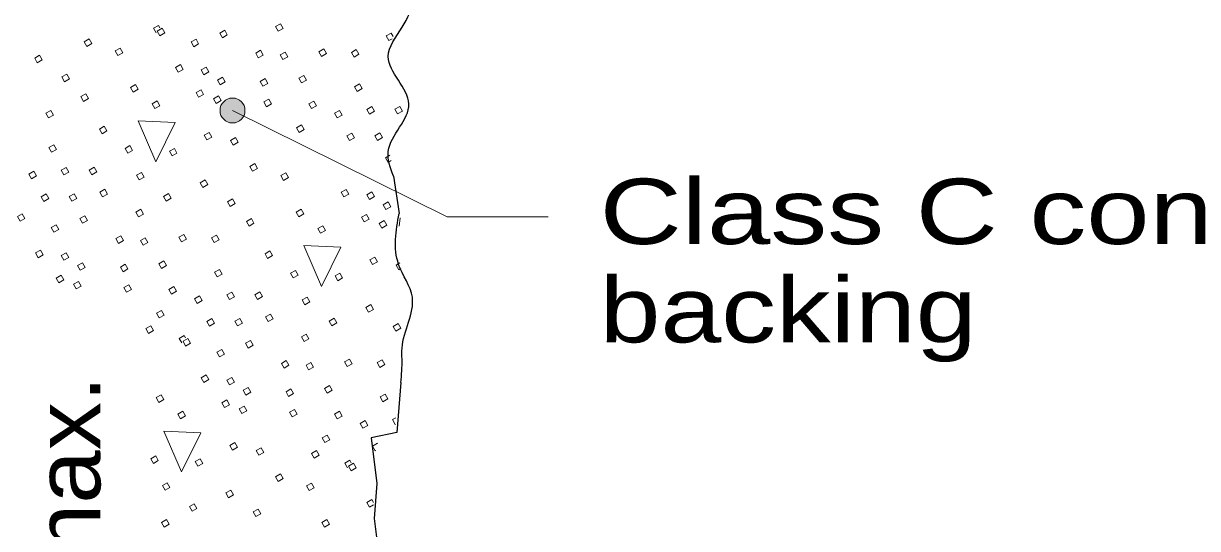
# Model space of a CAD drawing. Extents: x 1170.6 to 1204.6, y 975 to 1019.
# Drawn here: x 1195.183 to 1197.982, y 1000.634 to 1001.839 of the extents above; entities that cross this region are included whole.
import ezdxf
from ezdxf.enums import TextEntityAlignment as Align

# ---------------------------------------------------------------- set-up
doc = ezdxf.new("R2010")
doc.units = 0
doc.header["$LTSCALE"] = 0.062
doc.linetypes.add('LONG_DASHED', pattern=[7.5, 6, -1.5])
doc.layers.add('1', color=7, linetype='Continuous', lineweight=13)

msp = doc.modelspace()

# ---------------------------------------------------------------- hatches: boundary and pattern name
at = {"layer": '1'}
msp.add_hatch(color=256, dxfattribs=at).paths.add_polyline_path([(1195.71138, 1001.6317, 1), (1195.65182, 1001.6317, 1)])

# ---------------------------------------------------------------- linework, layer by layer
for p, q in [((1195.49925, 1001.81725), (1195.49317, 1001.82808)), ((1196.046, 1001.51883), (1196.05642, 1001.52475)), ((1196.07917, 1001.35608), (1196.08125, 1001.37567)), ((1196.0715, 1001.26292), (1196.0805, 1001.268)), ((1195.56058, 1001.077), (1195.5545, 1001.08783)), ((1196.06317, 1000.89408), (1196.07133, 1000.89875)), ((1195.9555, 1000.77942), (1195.94933, 1000.79025))]:
    msp.add_line(p, q, dxfattribs=at)
at = {"layer": '1', "lineweight": 25}
msp.add_line((1196.06508, 1001.47525), (1196.07867, 1001.38617), dxfattribs=at)
at = {"layer": '1'}
for points in [[(1195.49317, 1001.82808), (1195.505, 1001.83483), (1195.50825, 1001.82917)], [(1196.04825, 1001.80983), (1196.06017, 1001.81658), (1196.06475, 1001.80842)], [(1196.06242, 1001.80308), (1196.05467, 1001.79867), (1196.04825, 1001.80983)], [(1195.68158, 1001.63167), (1196.1935, 1001.37825), (1196.43392, 1001.37825)], [(1196.06008, 1001.512), (1196.05233, 1001.50758), (1196.046, 1001.51883)], [(1196.08258, 1001.25433), (1196.07783, 1001.25167), (1196.0715, 1001.26292)], [(1195.5545, 1001.08783), (1195.56633, 1001.09458), (1195.5695, 1001.08892)], [(1196.07008, 1000.88317), (1196.0695, 1000.88283), (1196.06317, 1000.89408)], [(1196.0155, 1000.83083), (1196.02733, 1000.83758), (1196.02742, 1000.83742)], [(1196.023, 1000.82025), (1196.02183, 1000.81958), (1196.0155, 1000.83083)], [(1195.94933, 1000.79025), (1195.96117, 1000.797), (1195.96442, 1000.79133)], [(1196.002, 1000.69658), (1196.01383, 1000.70325), (1196.01767, 1000.69642)], [(1196.01742, 1000.6905), (1196.00833, 1000.68533), (1196.002, 1000.69658)]]:
    msp.add_lwpolyline(points, dxfattribs=at)
for points in [[(1195.7845, 1001.83192), (1195.79633, 1001.83858), (1195.80267, 1001.82733), (1195.79083, 1001.82067)], [(1195.50225, 1001.82125), (1195.51408, 1001.828), (1195.5205, 1001.81675), (1195.50858, 1001.81)], [(1195.65108, 1001.81642), (1195.66292, 1001.82317), (1195.66925, 1001.81192), (1195.65742, 1001.80517)], [(1195.32783, 1001.79575), (1195.33967, 1001.8025), (1195.346, 1001.79125), (1195.33417, 1001.7845)], [(1195.40167, 1001.77375), (1195.4135, 1001.7805), (1195.41983, 1001.76925), (1195.408, 1001.76258)], [(1195.58275, 1001.79525), (1195.59458, 1001.80192), (1195.60092, 1001.79067), (1195.58908, 1001.784)], [(1195.88742, 1001.772), (1195.89925, 1001.77875), (1195.90558, 1001.7675), (1195.89375, 1001.76075)], [(1195.965, 1001.77033), (1195.97683, 1001.77708), (1195.98317, 1001.76583), (1195.97133, 1001.75908)], [(1195.20992, 1001.75692), (1195.22175, 1001.76367), (1195.22808, 1001.75242), (1195.21625, 1001.74567)], [(1195.73683, 1001.76867), (1195.74867, 1001.77533), (1195.755, 1001.76408), (1195.74317, 1001.75742)], [(1195.7955, 1001.76425), (1195.80733, 1001.77092), (1195.81367, 1001.75967), (1195.80183, 1001.753)], [(1195.54583, 1001.73442), (1195.55767, 1001.74117), (1195.564, 1001.72992), (1195.55217, 1001.72317)], [(1195.60683, 1001.72833), (1195.61867, 1001.735), (1195.625, 1001.72375), (1195.61317, 1001.71708)], [(1195.27483, 1001.71167), (1195.28667, 1001.71833), (1195.293, 1001.70717), (1195.28117, 1001.70042)], [(1195.43825, 1001.68683), (1195.45008, 1001.69358), (1195.45642, 1001.68233), (1195.44458, 1001.67567)], [(1195.64575, 1001.70425), (1195.65758, 1001.711), (1195.66392, 1001.69975), (1195.65208, 1001.693)], [(1195.74783, 1001.701), (1195.75967, 1001.70767), (1195.766, 1001.69642), (1195.75417, 1001.68975)], [(1195.83975, 1001.70875), (1195.85158, 1001.7155), (1195.85792, 1001.70425), (1195.84608, 1001.6975)], [(1195.97242, 1001.6885), (1195.98433, 1001.69517), (1195.99067, 1001.68392), (1195.97875, 1001.67725)], [(1195.31983, 1001.66475), (1195.33167, 1001.6715), (1195.338, 1001.66025), (1195.32617, 1001.6535)], [(1195.59458, 1001.6745), (1195.6065, 1001.68117), (1195.61283, 1001.67), (1195.60092, 1001.66325)], [(1195.63633, 1001.65992), (1195.64817, 1001.66667), (1195.6545, 1001.65542), (1195.64267, 1001.64867)], [(1195.49025, 1001.64767), (1195.50208, 1001.65442), (1195.50842, 1001.64317), (1195.49658, 1001.63642)], [(1195.75625, 1001.65208), (1195.76808, 1001.65875), (1195.77442, 1001.64758), (1195.76258, 1001.64083)], [(1195.86358, 1001.6475), (1195.87542, 1001.65417), (1195.88175, 1001.64292), (1195.86992, 1001.63625)], [(1196.00183, 1001.63442), (1196.01375, 1001.64108), (1196.02008, 1001.62983), (1196.00825, 1001.62317)], [(1196.06858, 1001.63475), (1196.08042, 1001.64142), (1196.08675, 1001.63017), (1196.07492, 1001.6235)], [(1195.2365, 1001.62517), (1195.24833, 1001.63192), (1195.25467, 1001.62067), (1195.24283, 1001.61392)], [(1195.92475, 1001.62525), (1195.93658, 1001.63192), (1195.943, 1001.62067), (1195.93108, 1001.614)], [(1195.36417, 1001.5875), (1195.376, 1001.59417), (1195.38233, 1001.583), (1195.3705, 1001.57625)], [(1195.4565, 1001.60692), (1195.499, 1001.50942), (1195.54467, 1001.60317)], [(1195.83408, 1001.59067), (1195.84592, 1001.59742), (1195.85233, 1001.58617), (1195.84042, 1001.57942)], [(1195.61408, 1001.57292), (1195.626, 1001.57958), (1195.63233, 1001.56842), (1195.6205, 1001.56167)], [(1195.67658, 1001.5605), (1195.68842, 1001.56717), (1195.69475, 1001.55592), (1195.68292, 1001.54925)], [(1195.95417, 1001.57108), (1195.96608, 1001.57783), (1195.97242, 1001.56658), (1195.9605, 1001.55992)], [(1196.02092, 1001.57142), (1196.03275, 1001.57817), (1196.03908, 1001.56692), (1196.02725, 1001.56025)], [(1195.24392, 1001.54333), (1195.25583, 1001.55008), (1195.26217, 1001.53883), (1195.25025, 1001.53208)], [(1195.42533, 1001.54108), (1195.43717, 1001.54783), (1195.4435, 1001.53658), (1195.43167, 1001.52992)], [(1195.53108, 1001.53442), (1195.54292, 1001.54117), (1195.54925, 1001.52992), (1195.53742, 1001.52317)], [(1195.72267, 1001.49817), (1195.7345, 1001.50492), (1195.74083, 1001.49367), (1195.729, 1001.48692)], [(1195.19625, 1001.48008), (1195.20817, 1001.48683), (1195.2145, 1001.47558), (1195.20258, 1001.46883)], [(1195.27342, 1001.48925), (1195.28525, 1001.496), (1195.29158, 1001.48475), (1195.27975, 1001.478)], [(1195.34008, 1001.48958), (1195.35192, 1001.49633), (1195.35825, 1001.48508), (1195.34642, 1001.47833)], [(1195.453, 1001.47717), (1195.46483, 1001.48392), (1195.47117, 1001.47267), (1195.45933, 1001.46592)], [(1195.79658, 1001.47625), (1195.80842, 1001.48292), (1195.81475, 1001.47167), (1195.80292, 1001.465)], [(1195.36517, 1001.437), (1195.377, 1001.44367), (1195.38333, 1001.43242), (1195.3715, 1001.42575)], [(1195.60483, 1001.45933), (1195.61667, 1001.46608), (1195.623, 1001.45483), (1195.61117, 1001.44808)], [(1195.94075, 1001.43683), (1195.95258, 1001.44358), (1195.95892, 1001.43233), (1195.94708, 1001.42558)], [(1195.22567, 1001.426), (1195.23758, 1001.43275), (1195.24392, 1001.4215), (1195.23208, 1001.41475)], [(1195.29242, 1001.42633), (1195.30425, 1001.43308), (1195.31058, 1001.42183), (1195.29875, 1001.41508)], [(1195.51742, 1001.42683), (1195.52925, 1001.43358), (1195.53558, 1001.42233), (1195.52375, 1001.41558)], [(1195.66975, 1001.41408), (1195.68158, 1001.42083), (1195.68792, 1001.40958), (1195.67608, 1001.40283)], [(1196.00167, 1001.43075), (1196.01358, 1001.43742), (1196.01992, 1001.42617), (1196.008, 1001.4195)], [(1196.04067, 1001.40667), (1196.0525, 1001.41342), (1196.05883, 1001.40217), (1196.047, 1001.39542)], [(1195.16867, 1001.37858), (1195.1805, 1001.38525), (1195.18683, 1001.374), (1195.175, 1001.36733)], [(1195.45083, 1001.38917), (1195.46275, 1001.39592), (1195.46908, 1001.38467), (1195.45717, 1001.37792)], [(1195.83317, 1001.38933), (1195.845, 1001.396), (1195.85133, 1001.38475), (1195.8395, 1001.37808)], [(1195.24917, 1001.3525), (1195.261, 1001.35925), (1195.26733, 1001.348), (1195.2555, 1001.34125)], [(1195.3175, 1001.37375), (1195.32933, 1001.38042), (1195.33567, 1001.36917), (1195.32383, 1001.3625)], [(1195.71467, 1001.36717), (1195.7265, 1001.37392), (1195.73283, 1001.36267), (1195.721, 1001.35592)], [(1195.9895, 1001.37692), (1196.00133, 1001.38358), (1196.00767, 1001.37242), (1195.99583, 1001.36567)], [(1196.03125, 1001.36233), (1196.04308, 1001.36908), (1196.04942, 1001.35783), (1196.03758, 1001.35117)], [(1195.40317, 1001.32592), (1195.415, 1001.33267), (1195.42142, 1001.32142), (1195.4095, 1001.31467)], [(1195.55383, 1001.32933), (1195.56567, 1001.33608), (1195.572, 1001.32483), (1195.56017, 1001.31808)], [(1195.63142, 1001.32758), (1195.64325, 1001.33433), (1195.64958, 1001.32308), (1195.63775, 1001.31642)], [(1195.88517, 1001.35008), (1195.897, 1001.35683), (1195.90333, 1001.34558), (1195.8915, 1001.33883)], [(1195.46192, 1001.3215), (1195.47375, 1001.32825), (1195.48008, 1001.317), (1195.46825, 1001.31025)], [(1195.85142, 1001.30933), (1195.89392, 1001.21183), (1195.9395, 1001.30558)], [(1195.21225, 1001.29175), (1195.22408, 1001.29842), (1195.23042, 1001.28717), (1195.21858, 1001.2805)], [(1195.27317, 1001.28558), (1195.28508, 1001.29233), (1195.29142, 1001.28108), (1195.27958, 1001.27433)], [(1195.75908, 1001.28992), (1195.77092, 1001.29667), (1195.77725, 1001.28542), (1195.76542, 1001.27867)], [(1196.009, 1001.27533), (1196.02083, 1001.28208), (1196.02717, 1001.27083), (1196.01533, 1001.26408)], [(1195.31217, 1001.26158), (1195.324, 1001.26825), (1195.33033, 1001.25708), (1195.3185, 1001.25033)], [(1195.41425, 1001.25825), (1195.42608, 1001.265), (1195.43242, 1001.25375), (1195.42058, 1001.247)], [(1195.50617, 1001.26608), (1195.518, 1001.27275), (1195.52433, 1001.26158), (1195.5125, 1001.25483)], [(1195.63883, 1001.24575), (1195.65067, 1001.2525), (1195.657, 1001.24125), (1195.64517, 1001.2345)], [(1195.82017, 1001.24358), (1195.832, 1001.25025), (1195.83842, 1001.239), (1195.8265, 1001.23233)], [(1195.261, 1001.23175), (1195.27283, 1001.2385), (1195.27917, 1001.22725), (1195.26733, 1001.2205)], [(1195.30275, 1001.21725), (1195.31458, 1001.224), (1195.32092, 1001.21275), (1195.30908, 1001.206)], [(1195.926, 1001.23683), (1195.93783, 1001.24358), (1195.94417, 1001.23233), (1195.93233, 1001.22558)], [(1195.42267, 1001.20933), (1195.4345, 1001.21608), (1195.44083, 1001.20483), (1195.429, 1001.19817)], [(1195.52992, 1001.20475), (1195.54175, 1001.2115), (1195.54817, 1001.20025), (1195.53625, 1001.1935)], [(1195.59117, 1001.1825), (1195.603, 1001.18925), (1195.60933, 1001.178), (1195.5975, 1001.17125)], [(1195.66825, 1001.19167), (1195.68008, 1001.19842), (1195.68642, 1001.18717), (1195.67458, 1001.18042)], [(1195.73492, 1001.192), (1195.74683, 1001.19875), (1195.75317, 1001.1875), (1195.74133, 1001.18075)], [(1195.84792, 1001.17958), (1195.85975, 1001.18633), (1195.86608, 1001.17508), (1195.85425, 1001.16833)], [(1195.99967, 1001.16175), (1196.0115, 1001.1685), (1196.01783, 1001.15725), (1196.006, 1001.15058)], [(1195.5005, 1001.148), (1195.51233, 1001.15475), (1195.51867, 1001.1435), (1195.50683, 1001.13675)], [(1195.62058, 1001.12842), (1195.63242, 1001.13517), (1195.63875, 1001.12392), (1195.62692, 1001.11717)], [(1195.68725, 1001.12875), (1195.69917, 1001.1355), (1195.7055, 1001.12425), (1195.69358, 1001.1175)], [(1195.76008, 1001.13942), (1195.77192, 1001.14608), (1195.77825, 1001.13492), (1195.76642, 1001.12817)], [(1195.91233, 1001.12925), (1195.92417, 1001.136), (1195.9305, 1001.12475), (1195.91867, 1001.11808)], [(1195.47533, 1001.11117), (1195.48717, 1001.11783), (1195.4935, 1001.10658), (1195.48167, 1001.09992)], [(1196.06467, 1001.1165), (1196.0765, 1001.12325), (1196.08283, 1001.112), (1196.071, 1001.10525)], [(1195.56358, 1001.081), (1195.57542, 1001.08767), (1195.58175, 1001.07642), (1195.56992, 1001.06975)], [(1195.71242, 1001.07617), (1195.72425, 1001.08283), (1195.73058, 1001.07158), (1195.71875, 1001.06492)], [(1195.84575, 1001.09158), (1195.85758, 1001.09833), (1195.86392, 1001.08708), (1195.85208, 1001.08033)], [(1195.64408, 1001.05492), (1195.65592, 1001.06167), (1195.66225, 1001.05042), (1195.65042, 1001.04367)], [(1195.79808, 1001.02833), (1195.80992, 1001.03508), (1195.81625, 1001.02383), (1195.80442, 1001.01708)], [(1195.85683, 1001.02392), (1195.86867, 1001.03067), (1195.875, 1001.01942), (1195.86317, 1001.01267)], [(1195.94875, 1001.03175), (1195.96058, 1001.0385), (1195.96692, 1001.02725), (1195.95508, 1001.0205)], [(1196.02625, 1001.03008), (1196.03817, 1001.03675), (1196.0445, 1001.0255), (1196.03267, 1001.01883)], [(1195.60708, 1000.99417), (1195.61892, 1001.00083), (1195.62533, 1000.98958), (1195.61342, 1000.98292)], [(1195.66808, 1000.988), (1195.67992, 1000.99475), (1195.68625, 1000.9835), (1195.67442, 1000.97675)], [(1195.707, 1000.964), (1195.71892, 1000.97075), (1195.72525, 1000.9595), (1195.71342, 1000.95275)], [(1195.80917, 1000.96067), (1195.821, 1000.96742), (1195.82733, 1000.95617), (1195.8155, 1000.94942)], [(1195.90108, 1000.9685), (1195.91292, 1000.97525), (1195.91925, 1000.964), (1195.90742, 1000.95725)], [(1195.49958, 1000.94658), (1195.51142, 1000.95333), (1195.51775, 1000.94208), (1195.50592, 1000.93533)], [(1195.65592, 1000.93417), (1195.66775, 1000.94092), (1195.67408, 1000.92967), (1195.66225, 1000.923)], [(1196.03375, 1000.94817), (1196.04558, 1000.95492), (1196.05192, 1000.94367), (1196.04008, 1000.93692)], [(1195.55158, 1000.90742), (1195.56342, 1000.91408), (1195.56975, 1000.90292), (1195.55792, 1000.89617)], [(1195.69767, 1000.91967), (1195.7095, 1000.92642), (1195.71583, 1000.91517), (1195.704, 1000.90842)], [(1195.81758, 1000.91175), (1195.82942, 1000.9185), (1195.83575, 1000.90725), (1195.82392, 1000.90058)], [(1195.92483, 1000.90717), (1195.93667, 1000.91392), (1195.943, 1000.90267), (1195.93117, 1000.89592)], [(1195.98608, 1000.88492), (1195.99792, 1000.89167), (1196.00425, 1000.88042), (1195.99242, 1000.87367)], [(1195.51783, 1000.86658), (1195.56033, 1000.76917), (1195.60592, 1000.86292)], [(1195.89542, 1000.85042), (1195.90725, 1000.85717), (1195.91358, 1000.84592), (1195.90175, 1000.83917)], [(1195.67542, 1000.83267), (1195.68725, 1000.83933), (1195.69358, 1000.82808), (1195.68175, 1000.82142)], [(1195.73792, 1000.82017), (1195.74975, 1000.82692), (1195.75608, 1000.81567), (1195.74425, 1000.80892)], [(1195.48658, 1000.80083), (1195.49842, 1000.80758), (1195.50475, 1000.79633), (1195.49292, 1000.78958)], [(1195.59242, 1000.79417), (1195.60425, 1000.80083), (1195.61058, 1000.78958), (1195.59875, 1000.78292)], [(1195.87025, 1000.81358), (1195.88208, 1000.82025), (1195.88842, 1000.80908), (1195.87658, 1000.80233)], [(1195.9585, 1000.78342), (1195.97033, 1000.79008), (1195.97667, 1000.77883), (1195.96483, 1000.77217)], [(1195.51433, 1000.73692), (1195.52617, 1000.74358), (1195.5325, 1000.73233), (1195.52067, 1000.72567)], [(1195.784, 1000.75792), (1195.79583, 1000.76467), (1195.80217, 1000.75342), (1195.79033, 1000.74667)], [(1195.85783, 1000.73592), (1195.86967, 1000.74267), (1195.876, 1000.73142), (1195.86417, 1000.72467)], [(1195.66608, 1000.71908), (1195.67792, 1000.72583), (1195.68425, 1000.71458), (1195.67242, 1000.70783)], [(1195.57875, 1000.68658), (1195.59058, 1000.69333), (1195.59692, 1000.68208), (1195.58508, 1000.67533)], [(1195.731, 1000.67383), (1195.74292, 1000.6805), (1195.74925, 1000.66925), (1195.73733, 1000.66258)], [(1195.51217, 1000.64892), (1195.524, 1000.65567), (1195.53033, 1000.64442), (1195.5185, 1000.63767)], [(1195.89442, 1000.649), (1195.90625, 1000.65575), (1195.91258, 1000.6445), (1195.90075, 1000.63775)]]:
    msp.add_lwpolyline(points, close=True, dxfattribs=at)
at = {"layer": '1', "lineweight": 25}
msp.add_lwpolyline([(1196.08308, 1000.98233), (1196.07375, 1000.86317), (1196.01233, 1000.85033), (1196.026, 1000.7415), (1196.01917, 1000.65825), (1196.026, 1000.60708)], dxfattribs=at)
at = {"layer": '1'}
msp.add_circle((1195.6816, 1001.6317), 0.02977, dxfattribs=at)
at = {"layer": '1', "lineweight": 25}
msp.add_ellipse((1192.33349, 1002.76462), major_axis=(0, 3.04986), ratio=0.944544, start_param=3.7685949, end_param=5.2606747, dxfattribs=at)
at = {"layer": '1', "linetype": 'LONG_DASHED'}
msp.add_ellipse((1192.32486, 1002.77617), major_axis=(0, 2.93373), ratio=0.944544, start_param=4.2344755, end_param=5.1344826, dxfattribs=at)
at = {"layer": '1', "lineweight": 25}
for points in [[(1196.06508, 1001.47525), (1196.05292, 1001.53425), (1196.10225, 1001.64742), (1196.05292, 1001.7605), (1196.08583, 1001.83017), (1196.11825, 1001.89608)], [(1196.08308, 1000.98233), (1196.08583, 1001.03825), (1196.08583, 1001.06442), (1196.11042, 1001.18625), (1196.07767, 1001.26458), (1196.07867, 1001.38617)]]:
    msp.add_spline(points, degree=3, dxfattribs=at)

# ---------------------------------------------------------------- texts
at = {"layer": '1'}
for s, width, p in [('Class C concrete', 1.3, (1196.55692, 1001.313)), ('backing', 1.25, (1196.55692, 1001.07833))]:
    msp.add_text(s, height=0.156, dxfattribs=dict(at, width=width)).set_placement(p)
at = {"layer": '1', "width": 1.1}
msp.add_text('max.', height=0.156, rotation=90, dxfattribs=at).set_placement((1195.36642, 1000.751), align=Align.CENTER)

doc.saveas('drawing.dxf')
